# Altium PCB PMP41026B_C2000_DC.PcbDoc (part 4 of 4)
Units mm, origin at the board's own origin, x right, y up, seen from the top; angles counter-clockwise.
Board outline 100 x 30 mm, 4 copper layers (Top Layer, Layer2-Plane, Layer3-Plane, Bottom Layer), stack 1.565 mm thick; 260 components, 175 nets, 797 pads, 279 vias.
Unrouted connection lines stored in the file: 19.
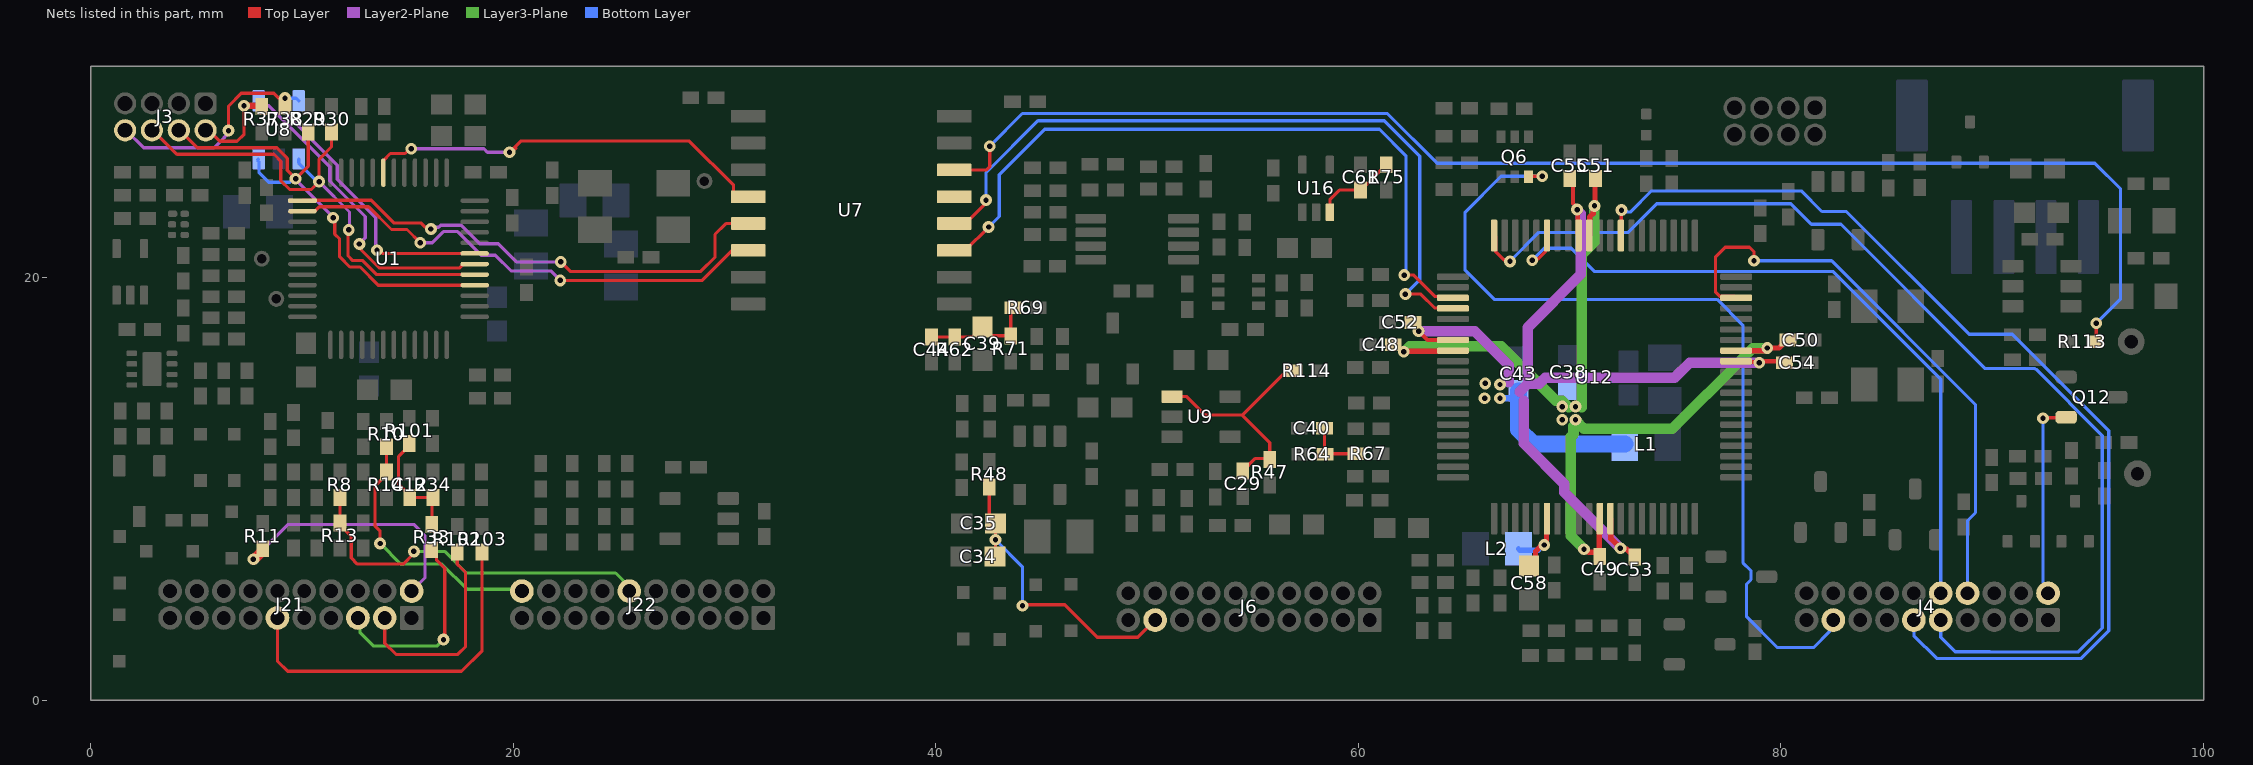
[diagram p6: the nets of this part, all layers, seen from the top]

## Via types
v1: diameter 0.559, hole 0.254, Top Layer to Bottom Layer, tented both sides, 274 vias
v2: diameter 1.27, hole 0.635, Top Layer to Bottom Layer, tented both sides, 3 vias
v3: diameter 0.559, hole 0.254, Top Layer to Bottom Layer, 2 vias

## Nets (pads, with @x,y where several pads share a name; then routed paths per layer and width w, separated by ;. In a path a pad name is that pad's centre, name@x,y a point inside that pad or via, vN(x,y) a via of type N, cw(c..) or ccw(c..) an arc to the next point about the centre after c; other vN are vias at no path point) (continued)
S_MCU_1V2: C38.2 C48.1 C49.1 C50.1 C51.1 U12.8 U12.31 U12.53 U12.71 | length 47
  Top Layer w0.254: C48.1@61.65,16.825 61.75,16.825 62.075,16.5 v1(62.15,16.5) 62.177,16.527 64.452,16.527 U12.8@64.475,16.55 ; v1(70.675,7.15) 70.757,7.15 70.895,7.013 71.342,7.013 71.402,7.073 71.402,8.577 U12.31@71.425,8.6 ; U12.71@70.925,22 70.948,22.023 70.948,22.866 71.117,23.034 71.117,23.342 v1(71.175,23.4) 71.2,23.425 71.2,24.675 C51.1@71.225,24.7 ; C49.1@71.322,6.993 71.425,6.89 C49.1@71.425,6.8 ; U12.53@77.875,16.55 v1@79.375,16.55 ; v1(79.35,16.675) 79.903,16.675 80.052,16.824 80.052,16.877 C50.1@80.225,17.05 ; C50.1@80.25,17.075 C50.1@80.225,17.05 ; C50.1@80.325,17.05 C50.1@80.225,17.05
  Layer3-Plane w0.5: v1(62.15,16.5) 62.166,16.5 62.426,16.76 66.765,16.76 69.35,14.175 69.65,14.175 69.95,13.875 ; 70.575,13.875 70.575,21.089 71.164,21.678 v1@71.164,23.4 ; v1(70.675,7.15) 70.675,7.166 70.05,7.791 70.05,12.475 70.181,12.606 70.181,12.975 70.318,13.113 70.438,13.113 70.438,13.087 70.677,12.848 74.848,12.848 76.493,14.493 76.507,14.493 78.671,16.657 79.29,16.657 79.297,16.664 79.339,16.664 v1(79.35,16.675)
  other v1: 69.65,13.275 70.275,13.275 69.65,13.9 70.275,13.9
S_MCU_3V3: C43.1 C52.1 C53.1 C54.1 C55.1 L1.2 U12.7 U12.32 U12.52 U12.72 | length 55.4
  Top Layer w0.203: C52.1@62.675,17.875 62.85,17.7 v1(62.85,17.475) 63.275,17.05 U12.7@64.475,17.05 ; C55.1@70,24.7 70.157,24.543 70.157,23.514 70.35,23.321 v1(70.35,23.225) 70.387,23.187 70.387,22.037 U12.72@70.425,22 ; U12.52@77.875,16.05 77.913,16.013 78.938,16.013 v1(78.975,15.975) 79.043,16.043 80.343,16.043 C54.1@80.473,16.173
  Top Layer w0.254: U12.32@71.925,8.6 71.948,8.577 71.948,7.652 v1(72.4,7.2) 72.458,7.142 72.708,7.142 C53.1@73.075,6.775 73.075,6.875 C53.1@72.902,7.048
  Layer2-Plane w0.5: v1(62.85,17.475) 65.5,17.475 67.125,15.85 67.125,15.048 ; 67.636,14.611 67.825,14.8 68.013,14.988 68.562,14.988 68.837,15.262 74.962,15.262 75.675,15.975 v1(78.975,15.975) ; 67.825,14.175 67.825,12.162 69.75,10.237 69.75,9.85 v1(72.4,7.2) ; 68.006,14.994 68.006,17.641 70.525,20.161 70.525,23.034 70.35,23.209 v1(70.35,23.225)
  Bottom Layer w0.203: v1(66.7,14.95) 67.275,14.95 C43.1@67.575,14.65
  Bottom Layer w0.3: v1(66.7,14.3) C43.1@67.425,14.3
  Bottom Layer w0.8: C43.1@67.575,14.65 67.575,12.825 68.275,12.125 L1.2@72.609,12.125
  other v1: 65.975,14.3 66,15
S_MCU_A_3V3: C58.2 L2.2 U12.26 | length 4
  Top Layer w0.254: C58.2@68.075,6.35 68.382,6.657 68.382,7.049 68.625,7.292 68.742,7.292 v1(68.8,7.35) 68.8,7.432 68.902,7.534 68.902,8.577 U12.26@68.925,8.6
  Bottom Layer w0.254: L2.2@67.575,7.175 67.643,7.107 68.51,7.107 68.753,7.35 v1(68.8,7.35)
S_SYNC/PLL: U7.13
SCI_RX0: U1.2 U7.6 | length 23.7
  Top Layer w0.152: U1.2@10.025,23.15 10.612,23.15 10.828,23.365 13.154,23.365 14.237,22.282 14.973,22.282 v1(15.597,21.658) ; v1(22.225,19.875) 28.95,19.875 30.37,21.295 U7.6@31.125,21.295
  Layer2-Plane w0.152: v1(15.597,21.658) 16.171,21.658 16.696,22.183 17.367,22.183 18.482,21.068 19.152,21.068 19.895,20.325 21.775,20.325 v1(22.225,19.875)
SCI_TX0: U1.1 U7.5 | length 24.3
  Top Layer w0.152: U1.1@10.025,23.65 10.045,23.67 13.28,23.67 14.363,22.587 15.642,22.587 15.843,22.387 16.026,22.387 v1(16.104,22.309) v1@16.07,22.275 ; v1(22.25,20.75) 22.7,20.3 28.875,20.3 29.55,20.975 29.55,22.05 30.065,22.565 U7.5@31.125,22.565
  Layer2-Plane w0.152: v1(16.104,22.309) 16.182,22.387 16.469,22.387 16.57,22.488 17.531,22.488 18.414,21.605 19.295,21.605 20.15,20.75 v1(22.25,20.75)
SMB_ALERT#: J4.17 Q6.6 | length 41.5
  Top Layer w0.152: Q6.6@68.05,24.775 68.075,24.8 v1(68.7,24.8)
  Bottom Layer w0.152: v1(68.7,24.8) 66.75,24.8 65.05,23.1 65.05,20.35 66.425,18.975 76.975,18.975 78.2,17.75 78.2,6.518 78.583,6.135 78.583,5.715 78.375,5.507 78.375,3.95 79.825,2.5 81.55,2.5 82.295,3.245 82.295,3.615 J4.17@82.48,3.8
SR-1H: J4.9 U12.80 | length 53.7
  Top Layer w0.152: U12.80@66.425,22 66.499,21.926 66.499,21.232 66.878,20.853 67.097,20.853 v1(67.175,20.775)
  Bottom Layer w0.152: v1(67.175,20.775) 68.545,22.145 72.77,22.145 74.125,23.5 80.469,23.5 81.442,22.527 82.841,22.527 89.668,15.7 92.025,15.7 92.065,15.66 92.077,15.66 95.21,12.528 95.21,3.422 94.078,2.29 89.909,2.29 89.899,2.3 88.25,2.3 87.56,2.99 J4.9@87.56,3.8
SR-1L: J4.11 U12.68 | length 49.9
  Top Layer w0.152: U12.68@72.425,22 72.438,22.012 72.438,23.187 v1(72.45,23.2)
  Bottom Layer w0.152: v1(72.45,23.2) 72.528,23.122 72.726,23.122 72.742,23.106 72.869,23.106 73.872,24.11 80.965,24.11 81.938,23.137 83.093,23.137 88.905,17.325 90.95,17.325 95.514,12.761 95.514,3.289 94.925,2.7 94.211,1.986 87.364,1.986 86.29,3.06 J4.11@86.29,3.8
SR-2H: J4.8 U12.58 | length 27.6
  Top Layer w0.152: U12.58@77.875,19.05 77.801,19.124 77.107,19.124 76.896,19.334 76.896,20.971 77.366,21.441 78.51,21.441 78.725,21.226 v1(78.725,20.8)
  Bottom Layer w0.152: v1(78.725,20.8) 82.394,20.8 89.208,13.986 89.208,8.883 88.83,8.505 J4.8@88.83,5.07
SR-2L: J4.10 U12.75 | length 33.9
  Top Layer w0.152: v1(68.225,20.825) 68.303,20.903 68.522,20.903 68.851,21.232 68.851,21.912 U12.75@68.932,21.993
  Bottom Layer w0.152: v1(68.225,20.825) 68.8,21.4 70.075,21.4 71.183,20.292 82.471,20.292 87.56,15.203 J4.10@87.56,5.07
SYNC/PLL: U1.43 U7.4 | length 20.1
  Top Layer w0.152: U1.43@13.85,24.975 13.85,25.547 14.185,25.882 14.881,25.882 15.102,26.103 v1(15.173,26.103) ; 20.115,26.129 19.928,25.942 v1(19.823,25.942) 20.351,26.47 28.33,26.47 30.427,24.373 30.427,24.059 30.651,23.835 U7.4@31.125,23.835
  Layer2-Plane w0.152: v1@15.239,26.17 v1(15.173,26.103) 18.617,26.103 18.778,25.942 v1(19.823,25.942)
TCK: J3.4 R29.2 U1.28 U8.3 | length 23.5
  Top Layer w0.152: J3.4@4.235,26.965 5.049,26.151 8.803,26.151 9.305,25.65 9.305,25.079 v1(9.7,24.683) 10.3,25.283 R29.2@10.3,26.9 R29.2@10.325,26.875 ; v1(11.475,22.837) 11.55,22.762 11.55,22.068 11.783,21.835 11.783,20.998 12.271,20.51 12.753,20.51 13.612,19.65 U1.28@18.175,19.65
  Layer2-Plane w0.152: v1(9.7,24.683) 9.7,24.648 11.475,22.873 v1(11.475,22.837)
  Bottom Layer w0.152: U8.3@7.95,25.625 7.892,25.567 7.964,25.495 7.964,24.986 8.429,24.521 9.428,24.521 9.59,24.683 v1(9.7,24.683) ; v1(11.475,22.837) v1@11.475,22.863
TDI: J3.8 R38.1 U1.31 U8.5 | length 24.4
  Top Layer w0.152: v1(6.522,26.964) 6.522,28.122 7.129,28.729 8.671,28.729 9.2,28.2 R38.1@9.2,28.1 ; v1(13.55,21.3) 13.66,21.3 13.81,21.15 U1.31@18.175,21.15
  Layer2-Plane w0.152: J3.8@1.695,26.965 2.509,26.151 5.842,26.151 6.319,26.628 6.319,26.651 6.522,26.854 v1(6.522,26.964) ; v1(9.2,28.5) 9.2,27.799 11.666,25.334 11.666,24.666 13.493,22.838 13.493,21.357 v1(13.55,21.3)
  Bottom Layer w0.152: v1(9.2,28.5) 9.725,28.5 U8.5@9.85,28.375
TDO: J3.6 R30.2 U1.29 U8.1 | length 24.4
  Top Layer w0.152: J3.6@2.965,26.965 4.084,25.846 8.677,25.846 9,25.523 9,24.6 9.425,24.175 10.436,24.175 v1(10.812,24.551) 10.812,25.612 11.4,26.2 R30.2@11.4,26.9 R30.2@11.425,26.875 ; v1(12.214,22.264) 12.178,22.228 12.178,21.034 12.398,20.814 12.879,20.814 13.543,20.15 U1.29@18.175,20.15
  Layer2-Plane w0.152: v1(10.812,24.551) 12.25,23.113 12.25,22.3 v1(12.214,22.264)
  Bottom Layer w0.152: U8.1@9.85,25.625 9.85,25.425 10.724,24.551 v1(10.812,24.551)
TEMP: C61.1 R75.2 U16.3 | length 4
  Top Layer w0.152: U16.3@58.65,23.1 58.65,23.7 59.1,24.15 C61.1@60.1,24.15 60.1,24.125 R75.2@61.325,25.35
TEMP_3: J21.5 R33.2 | length 9.6
  Top Layer w0.152: R33.2@16.15,7.125 16.374,6.901 16.374,6.631 16.754,6.251 16.754,2.929 v1(16.7,2.875)
  Layer3-Plane w0.152: J21.5@12.65,3.9 12.749,3.801 12.749,3.201 13.375,2.575 16.4,2.575 v1(16.7,2.875)
TEMP_3_MCU: C12.1 R33.1 R34.2 R101.2 | length 5.4
  Top Layer w0.152: R101.2@15.075,12.15 15.075,12.05 14.571,11.546 14.571,10.229 15.1,9.7 C12.1@15.1,9.6 R34.2@16.2,9.6 16.15,9.55 R33.1@16.15,8.325
TEMP_OUT: J21.11 R103.2 | length 17
  Top Layer w0.152: J21.11@8.84,3.9 8.84,1.86 9.325,1.375 17.55,1.375 18.525,2.35 R103.2@18.525,7.025
TMP_PRI: J21.3 R102.2 | length 10
  Top Layer w0.152: J21.3@13.92,3.9 13.92,2.705 14.45,2.175 17.375,2.175 17.739,2.539 17.739,6.061 17.6,6.2 17.35,6.45 R102.2@17.35,7.025
TMS: J3.2 R37.2 U1.30 U8.4 | length 21.8
  Top Layer w0.152: J3.2@5.505,26.965 5.602,26.965 6.111,26.456 6.926,26.456 7.259,26.789 v1(7.259,28.141) ; R37.2@8.059,28.141 R37.2@8.1,28.1 R37.2@8.1,27.832 ; R37.2@8.219,28.14 R37.2@8.324,28.035 ; v1(12.719,21.6) 12.796,21.522 12.796,21.328 13.669,20.455 17.455,20.455 17.593,20.593 17.593,20.622 17.62,20.65 U1.30@18.175,20.65
  Top Layer w0.3: v1(7.259,28.141) R37.2@8.059,28.141
  Layer2-Plane w0.152: v1(7.259,28.141) 8.428,28.141 11.32,25.248 11.32,24.58 13,22.9 13,21.892 12.719,21.611 v1(12.719,21.6)
  Bottom Layer w0.152: v1(7.259,28.141) 7.726,28.141 7.95,28.365 7.95,28.226 U8.4@8.174,28.002
URAT1_RX_s: U7.12 U12.4 | length 34.9
  Top Layer w0.152: U7.12@40.875,22.565 41.4,22.565 42.297,23.462 42.297,23.597 v1(42.375,23.675) ; v1(62.225,19.225) 62.95,19.225 63.605,18.57 64.455,18.57 U12.4@64.475,18.55
  Bottom Layer w0.152: v1(42.375,23.675) 42.375,24.975 44.83,27.43 61.22,27.43 62.9,25.75 62.9,19.9 v1(62.225,19.225)
URAT1_TX_s: U7.11 U12.3 | length 33.8
  Top Layer w0.152: U7.11@40.875,21.295 41.4,21.295 v1@42.5,22.395 ; v1(62.175,20.125) 62.625,20.125 63.643,19.107 64.418,19.107 U12.3@64.475,19.05
  Bottom Layer w0.152: v1(42.5,22.4) 43,22.9 43,24.875 45.15,27.025 61,27.025 62.25,25.775 62.25,20.2 v1(62.175,20.125)
VBB_FB: J22.12 R8.2 R13.2 | length 17.5
  Top Layer w0.152: R13.2@11.8,8.3 12.329,7.771 12.329,6.748 12.627,6.45 14.8,6.45 15.3,6.95 v1(15.3,7.05) ; R13.2@11.8,8.4 R8.2@11.8,9.6
  Layer3-Plane w0.152: v1(15.3,7.05) 16.75,7.05 17.775,6.025 24.845,6.025 25.49,5.38 J22.12@25.49,5.17
Vbulk_SNS: J22.20 R10.2 R14.2 | length 12.5
  Top Layer w0.152: v1(13.7,7.425) 13.7,8 13.46,8.24 13.46,10.16 14,10.7 R10.2@14,12
  Layer3-Plane w0.152: v1(13.7,7.425) 14.675,6.45 16.625,6.45 17.821,5.254 20.326,5.254 J22.20@20.41,5.17
Vcm_bias: C39.1 C44.1 R62.2 R69.1 R71.2 | length 5.5
  Top Layer w0.152: C44.1@39.8,17.2 R62.2@40.9,17.2 41.75,17.2 C39.1@42.2,17.65 ; C39.1@42.2,17.675 C39.1@42.2,17.65 ; R69.1@43.65,18.575 43.55,18.475 R71.2@43.55,17.25 42.625,17.25 42.624,17.251 42.599,17.251 C39.1@42.2,17.65
VCR-P: C40.1 R64.2 R67.2 | length 2.7
  Top Layer w0.152: C40.1@58.4,12.875 58.4,11.675 R64.2@58.425,11.65 58.45,11.675 R67.2@59.875,11.675
VCR_sns/CT2: C34.2 C35.2 J6.17 R48.1 | length 14.4
  Top Layer w0.152: R48.1@42.525,10.1 42.525,8.675 C35.2@42.825,8.375 v1(42.825,7.6) 42.825,6.825 C34.2@42.8,6.8 ; v1(44.1,4.475) 44.15,4.525 46.098,4.525 47.637,2.986 49.566,2.986 J6.17@50.38,3.8
  Bottom Layer w0.152: v1(42.825,7.6) 44.1,6.325 v1(44.1,4.475)
VINOK: J4.2 Q12.2 | length 9.5
  Top Layer w0.152: v1(92.4,13.35) 92.425,13.375 93.475,13.375 Q12.2@93.5,13.4
  Bottom Layer w0.152: v1(92.4,13.35) 92.4,5.572 92.64,5.332 J4.2@92.64,5.07
VINOK-s: R113.1 U7.14 | length 66
  Top Layer w0.152: U7.14@40.875,25.105 42.405,25.105 42.55,25.25 v1(42.55,26.225) ; R113.1@94.89,17.035 94.925,17.07 v1(94.925,17.85)
  Bottom Layer w0.152: v1(42.55,26.225) 44.1,27.775 61.369,27.775 63.727,25.417 94.858,25.417 96.075,24.2 96.075,19 v1(94.925,17.85)
Vo_SNS: C29.2 R47.2 R114.2 U9.1 | length 11.2
  Top Layer w0.152: U9.1@51.175,14.375 51.875,14.375 52.75,13.5 54.5,13.5 ; C29.2@54.525,10.85 55.125,11.45 55.75,11.45 R47.2@55.8,11.4 55.8,12.2 54.5,13.5 ; R114.2@56.95,15.6 56.766,15.416 56.416,15.416 54.5,13.5
ZCD_Amp: J21.2 R11.2 | length 12.6
  Top Layer w0.5: v1(7.7,6.675) 7.75,6.675 8.15,7.075 R11.2@8.15,7.175
  Layer2-Plane w0.154: v1(7.7,6.675) 9.35,8.325 15.3,8.325 15.825,7.8 15.825,5.805 J21.2@15.19,5.17
pads on no net: J3.7 J7.7 J21.12 J21.14 J21.16 J21.17 J22.7 J22.10 J22.15 U1.7 U3.1 U6.4 U7.7 U12.6 U12.11 U12.14 U12.15 U12.16 U12.22 U12.29 U12.33 U12.34 U12.38 U12.40 U12.44 U12.65 U12.67 U12.79 U16.1
copper on no net: | length 1
  Top Layer w0.203: 18.6,13 v1(19.6,13)

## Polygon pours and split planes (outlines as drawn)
S_3V3 on Layer3-Plane "S_3V3_L03_P090" (solid, remove dead copper, pour order 90): 39.35,0 99.8,0 99.8,30 39.35,30
MCU_1V2 on Layer3-Plane "MCU_1V2_L03_P088" (solid, remove dead copper, pour order 88): 13.3,27.2 13.9,27.8 19.3,27.8 22.95,24.15 22.95,20.65 22.5,20.2 22.5,16.3 20.9,14.7 20,14.7 19.5,15.2 19.5,15.7 20.1,16.3 21,17.2 21,23.4 19.4,25 14.2,25 13.3,25.9
3V3 on Layer3-Plane "3V3_L03_P089" (solid, remove dead copper, pour order 89): 0,25.704 6.1,25.704 6.604,25.2 6.604,23.804 7.8,22.609 11.304,22.609 15.796,18.117 15.796,16.1 17.791,14.105 17.791,12.618 19.1,11.2 19.1,9.9 19.4,9.6 19.4,8.1 20.6,6.9 20.6,4.6 21.2,4 30.95,4 32.625,5.675 32.625,30 0,30
MCU_3V3 on Layer3-Plane "MCU_3V3_L03_P086" (solid, remove dead copper, pour order 86): 21,20.8 20.6,20.4 18.8,20.4 16.95,22.25 14.75,22.25 13.3,23.7 12.7,23.7 11.7,24.7 11.7,27.1 12.2,27.6 12.9,27.6 13.3,27.2 13.3,25.9 14.2,25 19.4,25 21,23.4
3V3A on Layer3-Plane "3V3A_L03_P085" (solid, remove dead copper, pour order 85): 0,24.538 0.762,25.3 5.891,25.3 6.198,24.994 6.198,23.6 7.599,22.199 11.1,22.199 15.396,17.903 15.396,15.9 17.601,13.695 17.601,12.399 18.9,11.1 18.9,9.375 15.5,5.975 0,5.975
PGND on Layer2-Plane "PGND_L02_P079" (solid, remove dead copper, pour order 79): 31.85,30 12.362,30 1.4,30 0,28.6 0,1.6 32.7,1.6 32.7,29.15
S_AGND on Layer2-Plane "S_AGND_L02_P082" (solid, remove dead copper, pour order 82): 39.4,0 99.8,0 99.8,30 39.4,30
PGND on Bottom Layer "PGND_L04_P080" (solid, remove dead copper, pour order 80): 32.575,28.7 31.275,30 12.362,30 1.4,30 0,28.6 0,1.45 1.45,0 34.275,0 34.975,0.7 34.975,8.275 32.575,10.675
S_AGND on Top Layer "S_AGND_L01_P091" (solid, remove dead copper, pour order 91): 66.575,22.15 76.625,22.15 77.9,20.875 77.7,20.675 77.7,10.85 75.45,8.6 67,8.6 64.025,11.575 64.025,19.6

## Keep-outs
Keep-Out Layer:
  lines w0.254: 0,0 0,29.925 99.975,29.925 99.975,0 0,0

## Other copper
Top Layer:
  rectangle: 18.1,12.525 20.075,13.475
  text ".Layer_Name" at 11.565,-25.571 h1.52
Layer2-Plane:
  rectangle net S_MCU_3V3: 65.577,13.925 68.05,15.298
  pour cut-out: 43.74,21.265 48.85,26.375 56.869,26.375 58.515,24.729 58.515,17.125 58.8,17.125 58.8,24.725 56.975,26.55 48.675,26.55 43.45,21.325 43.45,18.075 39.325,18.075 39,17.75 43.74,17.75
  pour cut-out: 58.515,14.125 58.515,13.199 58.515,9.135 64.696,2.954 64.722,0.242 64.925,0.242 64.925,3.15 58.8,9.275 58.8,14.125
  pour cut-out: 95.793,2.343 96.25,2.8 96.975,2.8 97.446,2.329 97.446,1.596 97,1.15 96.243,1.15 95.81,1.583
  pour cut-out: 89.543,24.468 90,24.925 90.725,24.925 91.196,24.454 91.196,23.721 90.75,23.275 89.993,23.275 89.56,23.708
  pour cut-out: 17.599,13.697 15.396,15.9 15.396,17.903 11.1,22.199 8.4,22.199 7.698,22.901 6.897,22.901 6.198,23.6 6.198,24.994 5.9,25.291 0,25.291 -0.104,25.396 -0.104,25.6 0,25.704 6.1,25.704 6.604,25.2 6.604,23.804 7.105,23.303 7.803,23.303 8.498,22.609 11.304,22.609 15.796,18.117 15.796,16.1 17.998,13.898 17.998,12.601 19.299,11.299 19.299,9.7 19.2,9.6 19,9.6 18.9,9.7 18.9,11.1 17.6,12.4
  text ".layer_Name" at 11.387,-25.47 h1.52
Layer3-Plane:
  rectangle net S_MCU_1V2: 69.125,12.725 70.8,14.425
  pour cut-out: 17.599,13.697 15.396,15.9 15.396,17.903 11.1,22.199 8.4,22.199 7.698,22.901 6.897,22.901 6.198,23.6 6.198,24.994 5.9,25.291 0,25.291 -0.104,25.396 -0.104,25.6 0,25.704 6.1,25.704 6.604,25.2 6.604,23.804 7.105,23.303 7.803,23.303 8.498,22.609 11.304,22.609 15.796,18.117 15.796,16.1 17.998,13.898 17.998,12.601 19.299,11.299 19.299,9.7 19.2,9.6 19,9.6 18.9,9.7 18.9,11.1 17.6,12.4
  text ".layer_Name" at 11.641,-25.47 h1.52
Bottom Layer:
  rectangle net S_MCU_1V2: 69.4,12.95 70.675,15.2
  rectangle net S_MCU_3V3: 65.575,13.825 68.075,15.225
  pour cut-out: 17.599,13.697 15.396,15.9 15.396,17.903 11.1,22.199 8.4,22.199 7.698,22.901 6.897,22.901 6.198,23.6 6.198,24.994 5.9,25.291 0,25.291 -0.104,25.396 -0.104,25.6 0,25.704 6.1,25.704 6.604,25.2 6.604,23.804 7.105,23.303 7.803,23.303 8.498,22.609 11.304,22.609 15.796,18.117 15.796,16.1 17.998,13.898 17.998,12.601 19.299,11.299 19.299,9.7 19.2,9.6 19,9.6 18.9,9.7 18.9,11.1 17.6,12.4
  text ".Layer_Name" at 11.565,-25.571 h1.52

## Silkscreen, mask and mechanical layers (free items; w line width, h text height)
Top Overlay:
  circle w0.254: c6.5,29.25 r0.127
  text ".Layer_Name" at 11.565,-25.571 h1.52
Bottom Overlay:
  text ".Layer_Name" at 11.565,-25.571 h1.52
Top Paste:
  text ".Layer_Name" at 11.565,-25.571 h1.52
Bottom Paste:
  text ".Layer_Name" at 11.565,-25.571 h1.52
Top Solder:
  text ".Layer_Name" at 11.565,-25.571 h1.52
  text ".Layer_Name" at 11.565,-25.571 h1.52
Bottom Solder:
  text ".Layer_Name" at 11.565,-25.571 h1.52
M1 Board Outline:
  lines w0.254: 0,0 0,30 100,30 100,0 33.7,0 17.455,0 6.3,0 0,0
M2 Board Dimensions:
  rectangle: -3.091,-10.751 0.084,-7.576
  rectangle: 0.084,-13.926 9.609,-10.751
  lines w0.178: -3.091,-10.751 22.309,-10.751 ; 0.084,-13.926 0.084,-7.576 ; 3.259,-13.926 3.259,-7.576 ; 9.609,-13.926 9.609,-7.576 ; 15.959,-13.926 15.959,-7.576 ; -3.091,-13.926 22.309,-13.926 22.309,-7.576 -3.091,-7.576 -3.091,-13.926
  lines w0.254: 2.004,155.114 3.731,155.114 ; 3.071,154.377 3.756,155.088 ; 3.071,155.876 3.756,155.114 ; 3.934,189.277 5.661,191.36 ; 3.985,153.92 3.985,162.099 ; 3.985,163.14 5.255,161.769 8.049,161.769 9.243,163.216 ; 3.985,163.191 3.985,189.353 ; 5.636,191.385 7.262,189.175 ; 6.093,159.381 7.82,159.381 ; 7.16,158.644 7.846,159.356 ; 7.16,160.143 7.846,159.381 ; 7.287,189.15 9.116,191.436 ; 8.074,153.92 8.074,161.083 ; 9.243,163.191 9.243,189.353 9.243,191.512 ; 9.268,153.92 9.268,162.099 ; 9.42,179.717 cw(c7.998,161.743) 19.157,175.905 ; 9.467,179.682 ccw(c13.017,185.643) 10.76,179.083 ; 9.471,155.19 10.157,154.428 ; 9.471,155.215 10.157,155.927 ; 9.471,179.853 cw(c10.296,175.435) 11.064,179.863 ; 9.522,155.215 11.249,155.215 ; 9.522,159.356 10.208,158.594 ; 9.522,159.381 10.208,160.092 ; 9.573,159.381 11.3,159.381 ; 9.929,164.182 21.689,178.71 ; 17.803,176.272 ccw(c21.296,184.919) 19.191,175.834 ; 18.241,177.118 cw(c15.273,173.728) 19.225,175.891
  text "45" at 14.221,180.234 h1.52
  text "0.30mm" at 12.342,158.67 h1.52
  text "1.57mm" at 12.164,154.504 h1.52
  text "GOLD FINGER" at -0.054,148.484 h1.52
  text "SIDE VIEW" at 1.318,145.614 h1.52
M3 3D STEP Top:
  text ".Layer_Name" at 11.565,-25.571 h1.52
M4 3D STEP Bottom:
  text ".Layer_Name" at 11.565,-25.571 h1.52
M5 Assembly Top:
  lines w0.254: -10.507,-27.392 157.133,-27.392 ; -10.507,-22.227 157.183,-22.227 ; -10.507,-17.062 -10.507,-32.556 91.22,-32.556 157.183,-32.556 157.183,-17.062 -10.495,-17.062 -10.495,-32.556 29.523,-32.556 ; 52.104,-32.556 52.104,-17.062 ; 84.285,-22.227 84.285,-17.062 ; 105.621,-22.227 105.621,-17.062 ; 121.42,-32.722 121.42,-27.57
  text "COMPONENTS MARKED 'DNP' SHOULD NOT BE POPULATED." at 26.208,-11.855 h1.52
  text "ASSEMBLY VARIANT:" at 26.196,-14.789 h1.52
  text ".VariantName" at 52.51,-14.789 h1.52
  text "PCB VIEWED FROM TOP SIDE" at -8.895,-20.42 h1.52
  text "BOARD #:" at 54.009,-20.42 h1.52
  text "REV:" at 89.315,-20.42 h1.52
  text ".PCB_Rev" at 96.719,-20.42 h1.52
  text "SVN REV:" at 110.6,-20.42 h1.52
  text ".VersionControl_RevNumber" at 123.452,-20.42 h1.52
  text ".PRJ_Number" at 66.124,-20.898 h1.52
  text ".layer_Name" at 11.387,-25.47 h1.52
  text "TID #:" at 54.009,-25.584 h1.52
  text ".TID" at 67.864,-25.584 h1.52
  text "PLOT NAME =" at -8.895,-30.8 h1.52
  text ".plot_File_Name" at 11.565,-30.8 h1.52
  text "GENERATED    :" at 54.059,-30.8 h1.52
  text ".Print_Date" at 76.145,-30.8 h1.52
  text ".Print_Time" at 94.661,-30.8 h1.52
  text "TEXAS INSTRUMENTS" at 126.78,-30.8 h1.52
M6 Assembly Bottom:
  lines w0.254: -10.52,-22.24 157.171,-22.24 ; -10.469,-27.405 157.171,-27.405 ; 25.243,-32.734 25.243,-27.582 ; 41.042,-22.24 41.042,-17.075 ; 62.378,-22.24 62.378,-17.075 ; 94.56,-32.569 94.56,-17.075 ; 117.14,-32.569 157.158,-32.569 157.158,-17.075 -10.52,-17.075 -10.52,-32.569 55.444,-32.569 157.171,-32.569 157.171,-17.075
  text "COMPONENTS MARKED 'DNP' SHOULD NOT BE POPULATED." at 151.9,-11.843 h1.52
  text ".VariantName" at 125.383,-14.789 h1.52
  text "ASSEMBLY VARIANT:" at 151.773,-14.789 h1.52
  text ".VersionControl_RevNumber" at 23.211,-20.432 h1.52
  text "SVN REV:" at 36.063,-20.432 h1.52
  text ".PCB_Rev" at 49.945,-20.432 h1.52
  text "REV:" at 57.349,-20.432 h1.52
  text "BOARD #:" at 92.655,-20.432 h1.52
  text "PCB VIEWED FROM BOTTOM SIDE" at 155.558,-20.432 h1.52
  text ".PRJ_Number" at 80.909,-20.619 h1.52
  text ".layer_Name" at 136.89,-25.445 h1.52
  text ".TID" at 78.799,-25.597 h1.52
  text "TID #:" at 92.655,-25.597 h1.52
  text "TEXAS INSTRUMENTS" at 19.884,-30.812 h1.52
  text ".Print_Time" at 52.002,-30.812 h1.52
  text ".Print_Date" at 70.519,-30.812 h1.52
  text "GENERATED    :" at 92.604,-30.812 h1.52
  text ".plot_File_Name" at 135.098,-30.812 h1.52
  text "PLOT NAME =" at 155.558,-30.812 h1.52
M9 Title Sheet:
  drawing of 57 lines, arcs and shapes, not listed
  text "1" at 15.701,200.362 h1.78
  text "2" at 79.091,200.362 h1.78
  text "3" at 142.32,200.362 h1.78
  text "4" at 205.99,200.362 h1.78
  text "5" at 269.464,200.362 h1.78
  text "6" at 333.091,200.362 h1.78
  text "A" at -13.67,171.329 h1.78
  text "A" at 362.25,171.329 h1.78
  text "B" at -13.67,110.877 h1.78
  text "B" at 362.25,110.877 h1.78
  text "C" at -13.67,50.552 h1.78
  text "C" at 362.25,50.552 h1.78
  text "PROJECT TITLE:" at 285.034,3.283 h1.14
  text ".PRJ_Title" at 286.304,-0.104 h1.78
  text "DESIGNED FOR:" at 285.034,-4.362 h1.14
  text ".PRJ_Customer" at 286.304,-7.918 h1.78
  text "D" at -13.67,-9.646 h1.78
  text "D" at 362.25,-9.646 h1.78
  text "FILE NAME:" at 285.034,-11.982 h1.14
  text ".PCB_File_Name_No_Path" at 286.304,-15.03 h1.78
  text "Texas Instruments (TI) and/or its licensors do not warrant the accuracy or completeness of this specification" at 158.809,-19.141 h1.14
  text "ENGINEER:" at 285.034,-19.348 h1.14
  text "LAYOUT BY:" at 323.261,-19.348 h1.14
  text "or any information contained therein. TI and/or its licensors do not warrant that this design will meet" at 157.666,-22.003 h1.14
  text ".PRJ_Engineer" at 286.304,-23.285 h1.78
  text ".PCB_Layout" at 324.544,-23.285 h1.78
  text "the specifications, will be suitable for your application or fit for any particular purpose, or will operate in" at 157.666,-24.865 h1.14
  text "ALTIUM DESIGNER VERSION:" at 323.261,-27.222 h1.14
  text "an implementation. TI and/or its licensors do not warrant that the design is production worthy. You should" at 157.666,-27.726 h1.14
  text "completely validate and test your design implementation to confirm the system functionality for your application." at 158.809,-30.588 h1.14
  text ".print_Scale" at 286.304,-30.609 h1.78
  text ".Application_BuildNumber" at 324.544,-30.609 h1.78
  text "1" at 15.701,-35.858 h1.78
  text "2" at 79.091,-35.858 h1.78
  text "3" at 142.32,-35.858 h1.78
  text "4" at 205.99,-35.858 h1.78
  text "5" at 269.464,-35.858 h1.78
  text "6" at 333.091,-35.858 h1.78
M10 Fab Notes:
  drawing of 191 lines, arcs and shapes, not listed
  text "DESIGN INFORMATION" at 311.527,166.16 h1.52
  text "(REFER ALSO ARRAY/PANEL PROFILING INFORMATION)" at 302.343,162.053 h1.52
  text "BOARD SIZE" at 284.919,161.944 h1.52
  text "X" at 309.506,158.697 h1.52
  text "67.49MM" at 295.842,158.426 h1.52
  text "35MM" at 315.286,158.312 h1.52
  text "Number of Layers :" at 295.536,155.975 h1.52
  text "10" at 323.344,155.721 h1.52
  text "MIN. TRACK WIDTH:" at 295.536,152.444 h1.52
  text "6" at 322.702,152.455 h1.52
  text "MIL" at 327.311,152.444 h1.52
  text "MIN. CLEARANCE:" at 295.536,149.092 h1.52
  text "6" at 323.198,149.079 h1.52
  text "MIL" at 327.757,148.416 h1.52
  text "MIN. VIA PAD SIZE:" at 295.536,145.739 h1.52
  text "22" at 322.982,145.749 h1.52
  text "MIL" at 327.757,145.165 h1.52
  text "0.15mm (6MIL)" at 313.189,142.139 h1.52
  text "EXTERNAL" at 331.897,142.142 h1.52
  text "MINIMUM ANNULAR RING" at 287.174,142.031 h1.52
  text "PER" at 292.254,139.033 h1.52
  text "IPC-D-275 CLASS 2 LEVEL C" at 297.842,139.033 h1.52
  text "MIL, HOLES" at 335.643,136.181 h1.52
  text "+/-" at 325.674,136.163 h1.52
  text "+/-" at 347.366,136.163 h1.52
  text "REGISTRATION TOLERANCES:" at 287.174,136.036 h1.52
  text "METAL" at 317.648,136.036 h1.52
  text "5" at 332.283,136.036 h1.52
  text "3" at 353.442,136.036 h1.52
  text "MIL" at 356.394,136.036 h1.52
  text "IMPEDENCE CONTROLLED BOARD:NO" at 288.006,132.251 h1.52
  text "MATERIAL:" at 284.868,126.576 h1.52
  text "FR-4 High Tg" at 309.924,123.011 h1.52
  text "FR-408" at 295.562,122.793 h1.52
  text "OTHER" at 333.357,122.793 h1.52
  text "X" at 305.811,122.752 h1.52
  text "THICKNESS:" at 284.907,118.815 h1.52
  text "63 MIL (1.6mm) +/-10%" at 301.646,118.688 h1.52
  text "OTHER" at 336.329,118.552 h1.52
  text "X" at 298.217,118.485 h1.52
  text "TOLERANCE:" at 286.767,114.538 h1.52
  text "X" at 308.086,114.538 h1.52
  text "ANSI IPC-6012 TYPE 3 CLASS 2" at 312.834,114.538 h1.52
  text "OTHER +/-" at 312.834,110.576 h1.52
  text "BOW & TWIST:" at 286.767,106.588 h1.52
  text "X" at 308.086,106.588 h1.52
  text "ANSI IPC-6012 TYPE 3 CLASS 2" at 312.834,106.588 h1.52
  text "OTHER +/-" at 312.834,102.562 h1.52
  text "DRILLING:" at 284.868,99.044 h1.52
  text "REFERENCE:" at 286.767,96.073 h1.52
  text "X" at 303.232,96.073 h1.52
  text "AS SHOWN" at 307.982,96.073 h1.52
  text "X" at 326.118,96.073 h1.52
  text "NC_DRILL FILES" at 329.597,96.073 h1.52
  text "PTH MIN COPPER THICKNESS:" at 286.767,92.059 h1.52
  text "X" at 321.063,92.059 h1.52
  text "1MIL" at 324.543,92.059 h1.52
  text "OTHER" at 337.167,92.059 h1.52
  text "BOARD FINISH:" at 284.868,88.021 h1.52
  text "SILKSCREEN:" at 288.811,85.024 h1.52
  text "X" at 312.91,85.024 h1.52
  text "TOP" at 316.11,85.024 h1.52
  text "X" at 325.864,85.024 h1.52
  text "BOTTOM" at 329.089,85.024 h1.52
  text "SILKSCREEN COLOR:" at 288.811,80.782 h1.52
  text "X" at 312.883,80.782 h1.52
  text "WHITE" at 316.11,80.782 h1.52
  text "OTHER" at 329.089,80.782 h1.52
  text "SOLDER RESIST COLOR:" at 288.811,76.464 h1.52
  text "X" at 303.231,72.42 h1.52
  text "GREEN" at 306.458,72.42 h1.52
  text "BLUE" at 321.469,72.42 h1.52
  text "OTHER" at 335.135,72.42 h1.52
  text "IMMERSION GOLD (ENIG)" at 311.817,67.632 h1.52
  text "ENEPIG" at 345.791,67.548 h1.52
  text "SURFACE FINISH:" at 284.868,67.523 h1.52
  text "X" at 307.069,67.523 h1.52
  text "IMM. TIN/SILVER OR EQUIV" at 293.238,63.535 h1.52
  text "OTHER" at 329.598,63.535 h1.52
  text "X" at 324.743,63.502 h1.52
  text "HARD GOLD FINGERS" at 337.926,63.486 h1.52
  text "ARRAY/PANEL:" at 284.868,58.989 h1.52
  text "CUT AND TRIM PER MECH LAYER 1" at 311.818,58.88 h1.52
  text "N.C. ROUTE" at 311.817,55.026 h1.52
  text "V. SCORE" at 333.814,55.026 h1.52
  text "X" at 329.2,55 h1.52
  text "CERTIFICATION:" at 284.868,51.546 h1.52
  text "MATERIALS AND WORKMANSHIP FOR ALL PCBS" at 303.283,51.546 h1.52
  text "TO MEET OR EXCEED THE REQUIREMENTS OF:" at 303.283,49.057 h1.52
  text "X" at 293.796,45.59 h1.52
  text "ANSI IPC-A-600F CLASS ->" at 297.327,45.59 h1.52
  text "X" at 338.959,45.59 h1.52
  text "2" at 341.98,45.59 h1.52
  text "1" at 333.979,45.552 h1.52
  text "3" at 350.972,45.552 h1.52
  text "X" at 293.848,41.539 h1.52
  text "UL 94V-0" at 297.327,41.539 h1.52
  text "X" at 314.473,41.539 h1.52
  text "RoHS" at 317.952,41.539 h1.52
  text "OTHER" at 334.319,41.539 h1.52
  text "PER ORDER" at 344.405,41.539 h1.52
  text "ADDITIONAL REQUIREMENTS:" at 284.868,37.957 h1.52
  text "MICROSECTION:" at 286.767,35.036 h1.52
  text "YES" at 309.773,35.036 h1.52
  text "REQUIRED" at 331.655,31.07 h1.52
  text "BARE BOARD ELEC. TEST:" at 286.767,30.998 h1.52
  text "NONE" at 319.933,30.998 h1.52
  text "X" at 328.429,30.998 h1.52
  text "PER ORDER" at 346.692,30.998 h1.52
  text "MANUFACTURER'S UL:" at 286.767,27.01 h1.52
  text "RAIL" at 316.377,26.901 h1.52
  text "METAL" at 328.869,26.901 h1.52
  text "X" at 338.4,26.892 h1.52
  text "SILK" at 341.866,26.901 h1.52
  text "VIA`S TO BE TENTED:" at 286.253,22.142 h1.52
  text "NO" at 309.24,22.142 h1.52
M11 Gerber Information:
  lines w0.254: -10.507,-27.392 157.133,-27.392 ; -10.507,-22.227 157.183,-22.227 ; -10.507,-17.062 -10.507,-32.556 91.22,-32.556 157.183,-32.556 157.183,-17.062 -10.495,-17.062 -10.495,-32.556 29.523,-32.556 ; 52.104,-32.556 52.104,-17.062 ; 84.285,-22.227 84.285,-17.062 ; 105.621,-22.227 105.621,-17.062 ; 121.42,-32.722 121.42,-27.57
  text "ALL ARTWORK VIEWED FROM TOP SIDE" at -8.895,-20.42 h1.52
  text "BOARD #:" at 54.009,-20.42 h1.52
  text "REV:" at 89.315,-20.42 h1.52
  text ".PCB_Rev" at 96.719,-20.42 h1.52
  text "SVN REV:" at 110.6,-20.42 h1.52
  text ".VersionControl_RevNumber" at 123.452,-20.42 h1.52
  text ".PRJ_Number" at 66.251,-20.771 h1.52
  text "LAYER NAME =" at -8.895,-25.571 h1.52
  text "TID #:" at 54.009,-25.584 h1.52
  text ".TID" at 67.864,-25.584 h1.52
  text "PLOT NAME =" at -8.895,-30.8 h1.52
  text ".plot_File_Name" at 11.565,-30.8 h1.52
  text "GENERATED    :" at 54.059,-30.8 h1.52
  text ".Print_Date" at 76.145,-30.8 h1.52
  text ".Print_Time" at 94.661,-30.8 h1.52
  text "TEXAS INSTRUMENTS" at 126.78,-30.8 h1.52
M12 Stackup:
  drawing of 295 lines, arcs and shapes, not listed
  text "Layer" at 166.721,157.423 h1.52
  text "Name" at 177.133,157.423 h1.52
  text "Material" at 200.748,157.423 h1.52
  text "Thickness" at 222.586,157.423 h1.52
  text "Constant" at 239.092,157.423 h1.52
  text "Board Layer Stack" at 253.567,157.423 h1.52
  text "Top Overlay" at 177.133,154.375 h1.52
  text "Top Solder" at 177.133,151.327 h1.52
  text "Solder Resist" at 200.748,151.327 h1.52
  text "0.40mil" at 222.586,151.327 h1.52
  text "3.5" at 239.092,151.327 h1.52
  text "1" at 166.721,148.279 h1.52
  text "Top Layer" at 177.133,148.279 h1.52
  text "1.40mil" at 222.586,148.279 h1.52
  text "Dielectric1" at 177.133,145.231 h1.52
  text "FR-4 High Tg" at 200.748,145.231 h1.52
  text "8.00mil" at 222.586,145.231 h1.52
  text "4.2" at 239.092,145.231 h1.52
  text "2" at 166.721,142.183 h1.52
  text "Layer2-Plane" at 177.133,142.183 h1.52
  text "1.40mil" at 222.586,142.183 h1.52
  text "Dielectric 2" at 177.133,139.135 h1.52
  text "FR-4 High Tg" at 200.748,139.135 h1.52
  text "40.00mil" at 222.586,139.135 h1.52
  text "4.2" at 239.092,139.135 h1.52
  text "3" at 166.721,136.087 h1.52
  text "Layer3-Plane" at 177.133,136.087 h1.52
  text "1.40mil" at 222.586,136.087 h1.52
  text "Dielectric 3" at 177.133,133.039 h1.52
  text "FR-4 High Tg" at 200.748,133.039 h1.52
  text "8.00mil" at 222.586,133.039 h1.52
  text "4.2" at 239.092,133.039 h1.52
  text "4" at 166.721,129.991 h1.52
  text "Bottom Layer" at 177.133,129.991 h1.52
  text "1.40mil" at 222.586,129.991 h1.52
  text "Bottom Solder" at 177.133,126.943 h1.52
  text "Solder Resist" at 200.748,126.943 h1.52
  text "0.40mil" at 222.586,126.943 h1.52
  text "3.5" at 239.092,126.943 h1.52
  text "Bottom Overlay" at 177.133,123.895 h1.52
M13 Component Bodies Top:
  text ".Layer_Name" at 11.565,-25.571 h1.52
M14 Component Bodies Bottom:
  text ".Layer_Name" at 11.565,-25.571 h1.52
M15 Courtyards Top:
  text ".Layer_Name" at 11.565,-25.571 h1.52
M16 Courtyards Bottom:
  text ".Layer_Name" at 11.565,-25.571 h1.52
Drill Drawing:
  lines w0.254: 174.809,92.466 176.502,92.466 175.655,90.773 174.809,92.466 ; 174.809,94.583 174.809,95.006 175.232,95.43 174.809,95.853 174.809,96.276 175.232,96.276 175.655,95.853 176.079,96.276 176.502,96.276 176.502,95.853 176.079,95.43 176.502,95.006 176.502,94.583 176.079,94.583 175.655,95.006 175.232,94.583 174.809,94.583 ; 174.809,98.393 176.502,98.393 176.502,100.086 174.809,100.086 174.809,98.393 ; 174.809,102.626 175.232,102.626 175.232,102.203 176.079,102.203 176.079,102.626 176.502,102.626 176.502,103.473 176.079,103.473 176.079,103.896 175.232,103.896 175.232,103.473 174.809,103.473 174.809,102.626 ; 174.809,106.436 175.232,106.436 175.655,106.013 176.079,106.436 176.502,106.436 176.079,106.86 176.502,107.283 176.079,107.283 175.655,107.706 175.232,107.283 174.809,107.283 175.232,106.86 174.809,106.436
  lines w0.381: 173.29,89.63 271.816,89.63 ; 173.29,108.68 271.816,108.68 ; 187.282,85.82 187.282,112.49 ; 205.007,85.82 205.007,112.49 ; 239.185,85.82 239.185,112.49 ; 252.034,85.82 252.034,112.49 ; 173.29,85.82 271.816,85.82 271.816,112.49 173.29,112.49 173.29,85.82
  text "Symbol" at 175.576,109.823 h1.83
  text "Hit Count" at 188.425,109.823 h1.83
  text "Finished Hole Size" at 206.15,109.823 h1.83
  text "Plated" at 240.328,109.823 h1.83
  text "Hole Type" at 253.177,109.823 h1.83
  text "3" at 188.425,106.013 h1.52
  text "17.72mil (0.450mm)" at 206.15,106.013 h1.52
  text "PTH" at 240.328,106.013 h1.52
  text "Round" at 253.177,106.013 h1.52
  text "5" at 188.425,102.203 h1.52
  text "25.00mil (0.635mm)" at 206.15,102.203 h1.52
  text "PTH" at 240.328,102.203 h1.52
  text "Round" at 253.177,102.203 h1.52
  text "16" at 188.425,98.393 h1.52
  text "27.56mil (0.700mm)" at 206.15,98.393 h1.52
  text "PTH" at 240.328,98.393 h1.52
  text "Round" at 253.177,98.393 h1.52
  text "80" at 188.425,94.583 h1.52
  text "25.59mil (0.650mm)" at 206.15,94.583 h1.52
  text "PTH" at 240.328,94.583 h1.52
  text "Round" at 253.177,94.583 h1.52
  text "276" at 188.425,90.773 h1.52
  text "10.00mil (0.254mm)" at 206.15,90.773 h1.52
  text "PTH" at 240.328,90.773 h1.52
  text "Round" at 253.177,90.773 h1.52
  text "380 Total" at 188.425,86.963 h1.52
  text "DRILL TABLE" at 187.049,78.599 h1.52
  text "FOR 8MIL DRILL +0/-8MIL" at 186.968,76.13 h1.52
  text "FOR PTH +3/-3MIL" at 187.044,73.768 h1.52
  text "FOR NPTH +2/-2MIL" at 186.79,70.643 h1.52
  text "This is not impedence controlled board." at 186.868,67.645 h1.52
  text "Hard Gold Plating is required for TABS" at 186.334,64.775 h1.52
  text ".Layer_Name" at 11.565,-25.571 h1.52

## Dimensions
-3.091,-13.926 to 22.309,-13.926 on M2 Board Dimensions
0,30 to 0,0 on M2 Board Dimensions
0.025,30 to 105.025,30.2 on M2 Board Dimensions
23.172,-0.467 to 32.9,-10.5 on M2 Board Dimensions
43.15,29.2 to 43.425,17.2 on M2 Board Dimensions
33.7,0 to 33.7,0.975 on M2 Board Dimensions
